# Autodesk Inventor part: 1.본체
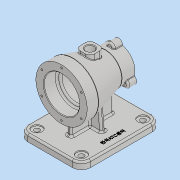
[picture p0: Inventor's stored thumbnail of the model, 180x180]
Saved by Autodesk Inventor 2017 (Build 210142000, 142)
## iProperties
Part Number: 1.본체
Material: 일반
Document SubType Name: Modeling
Designer: user
Density: 1 g/cm^3
Appearance: 기본값
Author: user
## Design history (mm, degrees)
sketch "스케치1"
  geometry: L1 (-50, 0)-(50, 0); L2 (-50, 0)-(-50, 45); L3 (-50, 45)-(-30, 45); L4 (-30, 45)-(27, 29); L5 (27, 29)-(50, 29); L6 (50, 29)-(50, 0); 2 further points
  constraints: 12 end point, 2 perpendicular, 1 coincident, 1 horizontal, 1 midpoint, 1 parallel, 1 vertical
  dimensions: "d0" = 100 distance of L1.start L1.end; "d1" = 45 distance of L1.start L2.end; "d2" = 20 distance of L2.end L3.end; "d3" = 58 diameter of L5 L1; "d4" = 23 distance of L4.end L5.end
revolve "회전1" sketch "스케치1" stored, may be unused: angle "d5" = 90 deg
node "작업 평면1"
sketch "스케치5"
  geometry: L1 (-70, -55)-(70, -55); L2 (70, -55)-(70, 55); L3 (70, 55)-(-70, 55); L4 (-70, 55)-(-70, -55); L5 (-70, -55)-(70, 55); L6 (70, -55)-(-70, 55); 1 further point
  constraints: 12 end point, 2 midpoint, 2 parallel, 1 horizontal, 1 perpendicular
  dimensions: "d34" = 140 distance of L3.end L2.end; "d35" = 110 distance of L2.end L1.end
extrude "돌출2" join sketch "스케치5" distance "d36" = 12; taper "d37" = 0 deg
sketch "스케치6"
  geometry: L1 (-37, -4)-(37, -4); L2 (37, -4)-(37, 4); L3 (37, 4)-(-37, 4); L4 (-37, 4)-(-37, -4); L5 (-37, -4)-(37, 4); L6 (37, -4)-(-37, 4); 1 further point
  constraints: 12 end point, 2 midpoint, 2 parallel, 1 horizontal, 1 perpendicular
  dimensions: "d38" = 74 distance of L3.end L2.end; "d39" = 8 distance of L2.end L1.end
extrude "돌출3" join sketch "스케치6" distance "d40" = 82; taper "d41" = 0 deg
sketch "스케치7"
  geometry: L1 (-70, -55)-(-70, 55) reference; L2 (0, 0)-(-70, 0); L3 (-70, 0)-(-70, -24); L4 (-70, -24)-(-4.155, -18.239); L5 (-70, 0)-(-70, 24); L6 (-70, 24)-(-4.155, 18.239); L7 (-4.155, 18.239)-(-4.155, -18.239)
  constraints: 12 end point, 2 point on line, 1 midpoint, 1 vertical
  dimensions: "d42" = 24 distance of L2.end L3.end; "d43" = 24 distance of L2.end L5.end; "d44" = 95 deg angle of L1 L6; "d45" = 95 deg angle of L1 L4; "d46" = 36.47868 distance of L6.end L4.end
extrude "돌출4" join sketch "스케치7" stored distance "d47" = 8; taper "d48" = 0 deg
sketch "스케치8"
  geometry: L1 (0, 0)-(0, 29); L2 (0, 0)-(25.115, -14.5); L3 (0, 0)-(-25.115, -14.5); C1 r 7 at (0, 29); C2 r 7 at (25.115, -14.5); C3 r 7 at (-25.115, -14.5); A1 r 29 centre (0, 0) between (4, -28.723) and (-4, -28.723) reference; A2 r 29 centre (0, 0) between (0, 29) and (25.115, -14.5)
  constraints: 6 end point, 6 point on circle, 4 centre point, 4 coincident
  dimensions: "d49" = 120 deg angle of L2 L1; "d50" = 120 deg angle of L2 L3; "d51" = 14 diameter of C1; "d52" = 14 diameter of C2; "d53" = 14 diameter of C3
extrude "돌출5" join sketch "스케치8" distance "d54" = 15; taper "d55" = 0 deg
sketch "스케치9"
  geometry: A1 r 7 centre (25.115, -43.5) between (20.909, -49.095) and (27.858, -37.06) reference; A2 r 7 centre (-25.115, -43.5) between (-27.858, -37.06) and (-20.909, -49.095) reference; 3 further points
  constraints: 2 coincident
hole "구멍3" sketch "스케치9" at (0, 0), (25.115, -43.5), (-25.115, -43.5) diameter "d56" = 3.242; stored, may be unused: countersink angle "d60" = 90 deg, drill point angle "d62" = 118 deg; dims "d57" = 9, "d58" = 4, "d59" = 2, "d61" = 11
sketch "스케치10"
  geometry: L1 (0, 40)-(0, -40); L2 (-34.641, 20)-(34.641, -20); L3 (-34.641, -20)-(34.641, 20); L4 (0, -40)-(0, 40); L5 (34.641, -20)-(-34.641, 20); L6 (34.641, 20)-(-34.641, -20); C1 r 45 at (0, 0) reference; C2 r 40 at (0, 0); 18 further points
  constraints: 14 coincident, 12 end point, 1 centre point, 1 midpoint, 1 vertical, 37 other
  dimensions: "d63" = 80 diameter of C2; "d64" = 80 distance of L1.start L1.end; "d67" = 360 deg dimension on C1.centre point (0, 40) (derived)
hole "구멍4" sketch "스케치10" at (0, 40), (0, -40), (-34.641, 20), (34.641, -20), (-34.641, -20), (34.641, 20) diameter "d69" = 3.242; stored, may be unused: countersink angle "d73" = 90 deg, drill point angle "d75" = 118 deg; dims "d70" = 9, "d71" = 4, "d72" = 2, "d74" = 11
sketch "스케치11"
  geometry: L1 (-50, -45)-(-50, 45) reference; L2 (-50, 0)-(50, 0); L3 (50, -8.06)-(50, 28.155) reference; L4 (-50, 0)-(-50, 31); L5 (-50, 31)-(-27, 31); L6 (-27, 31)-(-27, 25); L7 (-27, 25)-(20, 25); L8 (20, 25)-(20, 19); L9 (20, 19)-(50, 19); L10 (50, 0)-(50, 19); 1 further point
  constraints: 16 end point, 5 perpendicular, 3 point on line, 1 collinear, 1 horizontal, 1 midpoint
  dimensions: "d76" = 31 distance of L2.start L4.end; "d77" = 23 distance of L4.end L5.end; "d78" = 47 distance of L6.end L7.end; "d79" = 50 diameter of L7 L2; "d80" = 38 diameter of L9 L2
revolve "회전2" sketch "스케치11" stored, may be unused: angle "d81" = 90 deg
node "작업 평면2"
sketch "스케치12"
  geometry: L1 (-12.5, -12.5)-(12.5, -12.5); L2 (12.5, -12.5)-(12.5, 12.5); L3 (12.5, 12.5)-(-12.5, 12.5); L4 (-12.5, 12.5)-(-12.5, -12.5); L5 (-12.5, -12.5)-(12.5, 12.5); L6 (12.5, -12.5)-(-12.5, 12.5); 1 further point
  constraints: 12 end point, 2 midpoint, 2 parallel, 1 horizontal, 1 perpendicular
  dimensions: "d83" = 25 distance of L3.end L2.end; "d84" = 25 distance of L2.end L1.end
extrude "돌출6" join sketch "스케치12" stored distance "d85" = 15; taper "d86" = 0 deg
sketch "스케치13"
  geometry: C1 r 7.5 at (0, 0); 1 further point
  constraints: 1 centre point, 1 coincident
  dimensions: "d87" = 15 diameter of C1
extrude "돌출7" cut sketch "스케치13" stored distance "d88" = 0; taper "d89" = 0 deg
fillet "모깎기1" dims "d90" = 8
chamfer "모따기1" distance "d91" = 1; stored, may be unused: second distance "d92" = 2, angle "d93" = 45 deg
fillet "모깎기2" dims "d94" = 3
fillet "모깎기3" dims "d95" = 1
fillet "모깎기4" dims "d96" = 3
fillet "모깎기5" dims "d97" = 3
fillet "모깎기6" dims "d98" = 3
fillet "모깎기7" dims "d99" = 3
fillet "모깎기8" dims "d100" = 16
sketch "스케치14"
  geometry: A1 r 16 centre (-54, -39) between (-70, -39) and (-54, -55) reference; A2 r 16 centre (54, -39) between (54, -55) and (70, -39) reference; A3 r 16 centre (54, 39) between (70, 39) and (54, 55) reference; A4 r 16 centre (-54, 39) between (-54, 55) and (-70, 39) reference; 5 further points
  constraints: 4 coincident
hole "구멍5" sketch "스케치14" at (54, 39), (54, -39), (-54, -39), (-54, 39) diameter "d101" = 9; stored, may be unused: countersink angle "d105" = 90 deg, drill point angle "d107" = 118 deg; dims "d102" = 9, "d103" = 18, "d104" = 2, "d106" = 30
fillet "모깎기9" dims "d108" = 3
chamfer "모따기2" distance "d109" = 1; stored, may be unused: second distance "d110" = 2, angle "d111" = 45 deg
chamfer "모따기3" distance "d112" = 1; stored, may be unused: second distance "d113" = 2, angle "d114" = 45 deg
sketch "스케치15"
  geometry: L1 (-7, 20.726)-(-7, 7) reference; L2 (1, 26.749)-(-1, 26.749) reference; L3 (7, 7)-(7, 20.726) reference; L4 (34, 7)-(7, 7) reference; L5 (40, -1)-(40, 1) reference; L6 (7, -7)-(34, -7) reference; L7 (7, -20.726)-(7, -7) reference; L8 (-1, -26.749)-(1, -26.749) reference; L9 (-7, -7)-(-7, -20.726) reference; L10 (-34, -7)-(-7, -7) reference; L11 (-40, 1)-(-40, -1) reference; L12 (-7, 7)-(-34, 7) reference; L13 (-54, -55)-(54, -55) reference; L14 (70, -39)-(70, 39) reference; L15 (54, 55)-(-54, 55) reference; L16 (-70, 39)-(-70, -39) reference; C1 r 9 at (-54, -39) reference; C2 r 9 at (54, 39) reference; C3 r 9 at (54, -39) reference; C4 r 9 at (-54, 39) reference; A1 r 6 centre (34, 1) between (40, 1) and (34, 7) reference; A2 r 6 centre (34, -1) between (34, -7) and (40, -1) reference; A3 r 6 centre (-34, -1) between (-40, -1) and (-34, -7) reference; A4 r 6 centre (-34, 1) between (-34, 7) and (-40, 1) reference; A5 r 16 centre (-54, -39) between (-70, -39) and (-54, -55) reference; A6 r 16 centre (54, -39) between (54, -55) and (70, -39) reference; A7 r 16 centre (54, 39) between (70, 39) and (54, 55) reference; A8 r 16 centre (-54, 39) between (-54, 55) and (-70, 39) reference; 5 further points; 4 other entities
  constraints: 4 other
sketch "스케치16"
  geometry: L1 (-70, -70)-(-70, -82) reference; L2 (-50, -45)-(-50, 45) reference; L3 (-37, -47.99)-(-37, -67) reference; L4 (37, -67)-(37, -31.984) reference; 1 further point
  dimensions: "d115" = 20 distance between parallel lines of L1 L2 (derived); "d116" = 33 distance between parallel lines of L1 L3 (derived); "d117" = 74 distance between parallel lines of L4 L3 (derived)
fillet "모깎기10" dims "d118" = 3
node "작업 평면3"
sketch "스케치17"
  geometry: L1 (54, 55)-(-54, 55) reference; L2 (0, 55)-(0, 40); 3 further points
  constraints: 2 coincident, 2 end point, 1 midpoint, 1 vertical, 1 other
  dimensions: "d120" = 15 distance of L2.start L2.end
feature "엠보싱1" sketch "스케치17" dims "d0" = 100, "d1" = 45, "d2" = 20, "d3" = 58, "d4" = 23, "d121" = 0.5, "d122" = 0
fillet "모깎기11" dims "d123" = 1
node "솔리드1"
other parameters: "d33" = -82, "d82" = 45, "d119" = -62.5
